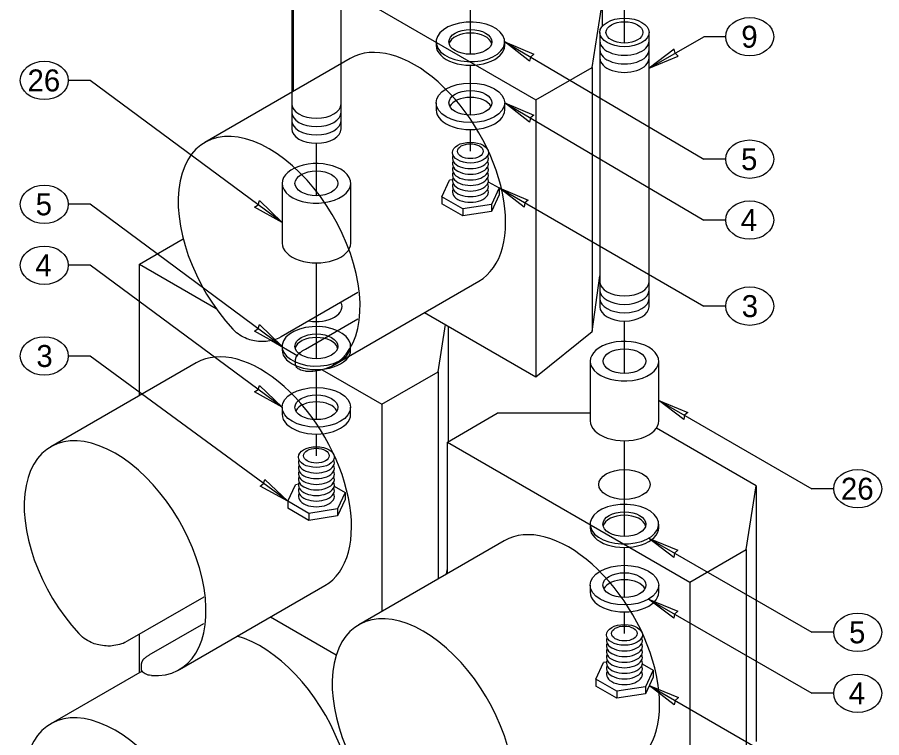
# Model space of a CAD drawing. Extents: x 99862 to 104211, y 98939 to 105076.
# Drawn here: x 100722 to 101352, y 103733 to 104258 of the extents above; entities that cross this region are included whole.
import ezdxf

# ---------------------------------------------------------------- set-up
doc = ezdxf.new("R2010")
doc.units = 0
for name, color, linetype in [('Level 11', 7, 'Continuous'), ('Level 15', 7, 'Continuous'), ('Level 19', 7, 'Continuous'), ('Level 2', 7, 'Continuous'), ('Level 20', 7, 'Continuous'), ('Level 26', 7, 'Continuous'), ('Level 3', 7, 'Continuous'), ('Level 4', 7, 'Continuous'), ('Level 5', 7, 'Continuous'), ('Level 7', 7, 'Continuous'), ('Level 9', 7, 'Continuous')]:
    doc.layers.add(name, color=color, linetype=linetype)

msp = doc.modelspace()

# ---------------------------------------------------------------- linework, layer by layer
at = {"layer": 'Level 11'}
for p, q in [((101027.62, 104240.09), (101027.62, 104237.54)), ((101077.62, 104237.54), (101077.62, 104240.09)), ((101027.62, 104195.66), (101027.62, 104190.56)), ((101077.62, 104190.56), (101077.62, 104195.66)), ((100915.33, 104018.13), (100915.33, 104015.58)), ((100965.33, 104015.58), (100965.33, 104018.13)), ((100915.33, 103973.7), (100915.33, 103968.6)), ((100965.33, 103968.6), (100965.33, 103973.7)), ((101139.89, 103888.48), (101139.89, 103885.93)), ((101189.89, 103885.93), (101189.89, 103888.48)), ((101139.89, 103844.06), (101139.89, 103838.95)), ((101189.89, 103838.95), (101189.89, 103844.06))]:
    msp.add_line(p, q, dxfattribs=at)
for centre in [(101052.62, 104240.09), (101052.62, 104195.66), (100940.33, 104018.13), (100940.33, 103973.7), (101164.89, 103888.48), (101164.89, 103844.06)]:
    msp.add_ellipse(centre, major_axis=(15.62, 0), ratio=0.57735, dxfattribs=at)
for centre, major_axis, start_param, end_param in [((101052.62, 104237.54), (-15.62, 0), 3.28349, 6.141288), ((101052.62, 104237.54), (-25, 0), 0, 3.141593), ((101052.62, 104190.56), (-15.62, 0), 3.428349, 5.996429), ((101052.62, 104190.56), (-25, 0), 6.283185, 9.424778), ((100940.33, 104015.58), (-15.62, 0), 3.28349, 6.141288), ((100940.33, 104015.58), (-25, 0), 0, 3.141593), ((100940.33, 103968.6), (-15.62, 0), 3.428349, 5.996429), ((100940.33, 103968.6), (-25, 0), 6.283185, 9.424778), ((101164.89, 103885.93), (-15.62, 0), 3.28349, 6.141288), ((101164.89, 103885.93), (-25, 0), 0, 3.141593), ((101164.89, 103838.95), (-15.62, 0), 3.428349, 5.996429), ((101164.89, 103838.95), (-25, 0), 6.283185, 9.424778)]:
    msp.add_ellipse(centre, major_axis=major_axis, ratio=0.57735, start_param=start_param, end_param=end_param, dxfattribs=at)
at = {"layer": 'Level 15'}
for p, q in [((101052.62, 104231.07), (101052.62, 104353.08)), ((101164.89, 104239.21), (101164.89, 104281.96)), ((101077.62, 104240.09), (101222.73, 104154.6)), ((101182.95, 104220.9), (101222.73, 104243.87)), ((101238.73, 104243.87), (101222.73, 104243.87)), ((101052.62, 104186.64), (101052.62, 104223.11)), ((100775.49, 104212), (100759.49, 104212)), ((100915.38, 104108.43), (100775.49, 104212)), ((101077.62, 104195.66), (101222.73, 104110.18)), ((101052.62, 104160.39), (101052.62, 104176.13)), ((100940.33, 104127.95), (100940.33, 104166.23)), ((101238.73, 104154.6), (101222.73, 104154.6)), ((101073.53, 104133.61), (101222.73, 104047.44)), ((100775.49, 104121.67), (100759.49, 104121.67)), ((100915.33, 104018.13), (100775.49, 104121.67)), ((101238.73, 104110.18), (101222.73, 104110.18)), ((100775.49, 104077.25), (100759.49, 104077.25)), ((100915.33, 103973.7), (100775.49, 104077.25)), ((100940.33, 104009.11), (100940.33, 104078.97)), ((101238.73, 104047.44), (101222.73, 104047.44)), ((101164.89, 103998.3), (101164.89, 104036.59)), ((100775.49, 104011.08), (100759.49, 104011.08)), ((100919.42, 103905.18), (100775.49, 104011.08)), ((100940.33, 103964.68), (100940.33, 104001.14)), ((101189.95, 103978.73), (101301.48, 103914.33)), ((100940.33, 103938.42), (100940.33, 103954.17)), ((101164.89, 103879.46), (101164.89, 103949.33)), ((101317.48, 103914.33), (101301.48, 103914.33)), ((101182.57, 103878.28), (101301.48, 103809.63)), ((101164.89, 103835.04), (101164.89, 103871.5)), ((101182.57, 103833.85), (101301.48, 103765.2)), ((101164.89, 103808.78), (101164.89, 103824.52)), ((101317.48, 103809.63), (101301.48, 103809.63)), ((101183.01, 103770.87), (101301.48, 103702.47)), ((101317.48, 103765.2), (101301.48, 103765.2))]:
    msp.add_line(p, q, dxfattribs=at)
for points in [[(101077.62, 104240.09), (101098.8, 104231.08), (101096.38, 104229.04), (101095.77, 104225.93)], [(101182.95, 104220.9), (101204.21, 104229.73), (101201.81, 104231.79), (101201.23, 104234.9)], [(101077.62, 104195.66), (101098.8, 104186.65), (101096.38, 104184.61), (101095.77, 104181.5)], [(101073.53, 104133.61), (101094.79, 104124.78), (101092.38, 104122.73), (101091.81, 104119.61)], [(100915.38, 104108.43), (100895.26, 104119.61), (100897.88, 104121.39), (100898.81, 104124.41)], [(100915.33, 104018.13), (100895.21, 104029.31), (100897.83, 104031.09), (100898.76, 104034.11)], [(100915.33, 103973.7), (100895.21, 103984.89), (100897.83, 103986.66), (100898.76, 103989.69)], [(101189.95, 103978.73), (101211.21, 103969.9), (101208.8, 103967.84), (101208.22, 103964.73)], [(100919.42, 103905.18), (100899.26, 103916.31), (100901.88, 103918.09), (100902.8, 103921.12)], [(101182.57, 103878.28), (101203.84, 103869.45), (101201.43, 103867.39), (101200.85, 103864.28)], [(101182.57, 103833.85), (101203.84, 103825.02), (101201.43, 103822.96), (101200.85, 103819.85)], [(101183.01, 103770.87), (101204.27, 103762.04), (101201.86, 103759.98), (101201.28, 103756.87)]]:
    msp.add_lwpolyline(points, close=True, dxfattribs=at)
at = {"layer": 'Level 19'}
for p, q in [((101141.29, 104029.03), (101146.95, 104069.49)), ((101100.34, 103995.93), (101141.29, 104029.03)), ((101035.32, 103852.16), (101035.84, 103855.87))]:
    msp.add_line(p, q, dxfattribs=at)
at = {"layer": 'Level 2'}
for p, q in [((101073.53, 104133.61), (101067.93, 104121.54)), ((101047.01, 104118.31), (101031.7, 104127.14)), ((101067.93, 104121.54), (101047.01, 104118.31)), ((101067.93, 104121.54), (101067.93, 104116.44)), ((101047.01, 104118.31), (101047.01, 104113.2)), ((100961.24, 103911.65), (100955.64, 103899.58)), ((100934.73, 103896.34), (100919.42, 103905.18)), ((100955.64, 103899.58), (100934.73, 103896.34)), ((100955.64, 103899.58), (100955.64, 103894.48)), ((100934.73, 103896.34), (100934.73, 103891.24)), ((101185.81, 103782.01), (101180.2, 103769.93)), ((101159.29, 103766.7), (101143.98, 103775.54)), ((101180.2, 103769.93), (101159.29, 103766.7)), ((101159.29, 103766.7), (101159.29, 103761.6)), ((101180.2, 103769.93), (101180.2, 103764.83))]:
    msp.add_line(p, q, dxfattribs=at)
for centre in [(101052.62, 104160.39), (100940.33, 103938.42), (101164.89, 103808.78)]:
    msp.add_ellipse(centre, major_axis=(-9.38, 0), ratio=0.57735, dxfattribs=at)
for centre, start_param, end_param in [((101052.62, 104155.28), 2.86885, 6.555928), ((101052.62, 104151.2), 2.86885, 6.555928), ((101052.62, 104147.04), 2.86338, 6.561398), ((101052.62, 104143.04), 2.874311, 6.550467), ((101052.62, 104138.95), 2.86885, 6.555928), ((101052.62, 104134.87), 2.86885, 6.555928), ((100940.33, 103933.32), 2.86885, 6.555928), ((100940.33, 103929.24), 2.86885, 6.555928), ((100940.33, 103925.08), 2.86338, 6.561398), ((100940.33, 103916.99), 2.86885, 6.555928), ((100940.33, 103921.07), 2.874311, 6.550467), ((100940.33, 103912.91), 2.86885, 6.555928), ((101164.89, 103803.68), 2.86885, 6.555928), ((101164.89, 103799.59), 2.86885, 6.555928), ((101164.89, 103795.43), 2.86338, 6.561398), ((101164.89, 103791.43), 2.874311, 6.550467), ((101164.89, 103787.35), 2.86885, 6.555928), ((101164.89, 103783.26), 2.86885, 6.555928)]:
    msp.add_ellipse(centre, major_axis=(13.12, 0), ratio=0.57735, start_param=start_param, end_param=end_param, dxfattribs=at)
at = {"layer": 'Level 20'}
for centre in [(101256.23, 104243.87), (100741.99, 104212), (101256.23, 104154.6), (100741.99, 104121.67), (101256.23, 104110.18), (100741.99, 104077.25), (101256.23, 104047.44), (100741.99, 104011.08), (101334.98, 103914.33), (101334.98, 103809.63), (101334.98, 103765.2)]:
    msp.add_ellipse(centre, major_axis=(-17.5, 0), ratio=0.8, dxfattribs=at)
at = {"layer": 'Level 26'}
for p, q in [((100923.56, 104204.06), (100923.56, 104299.94)), ((100923.56, 104299.94), (101100.34, 104197.87)), ((101141.29, 104221.52), (101148.63, 104268.14)), ((101148.63, 104268.14), (101148.63, 104251.39)), ((100965.07, 104228.03), (100859.01, 104166.79)), ((101100.34, 104197.87), (101141.29, 104221.52)), ((101141.29, 104221.52), (101141.29, 104029.03)), ((101100.34, 104197.87), (101100.34, 103995.93)), ((100811.28, 104077.98), (100843.31, 104096.47)), ((100811.28, 103982.11), (100811.28, 104077.98)), ((100811.28, 104077.98), (100867.3, 104045.63)), ((100952.76, 104004.42), (101058.82, 104065.65)), ((100970.59, 104057.31), (100914.72, 104025.05)), ((100932.4, 104016.13), (100970.47, 104038.11)), ((101019.2, 104042.77), (101100.34, 103995.93)), ((101029.02, 103999.56), (101034.43, 104033.97)), ((101036.36, 104032.87), (101036.36, 103948.63)), ((100907.62, 104022.35), (100926.74, 104011.32)), ((100852.79, 104006.07), (100746.73, 103944.84)), ((100925.08, 104005.69), (100925.08, 104007)), ((100944.46, 104001.08), (100988.06, 103975.91)), ((100988.06, 103975.91), (101029.02, 103999.56)), ((101029.02, 103999.56), (101029.02, 103848.52)), ((100988.06, 103975.91), (100988.06, 103824.87)), ((101035.84, 103948.33), (101072.16, 103969.3)), ((101139.95, 103969.3), (101072.16, 103969.3)), ((101260.91, 103916.53), (101188.22, 103958.5)), ((101035.84, 103852.46), (101035.84, 103948.33)), ((101035.84, 103948.33), (101212.62, 103846.27)), ((101253.57, 103869.91), (101260.91, 103916.53)), ((101260.91, 103916.53), (101260.91, 103729.92)), ((101077.35, 103876.42), (100971.29, 103815.19)), ((101212.62, 103846.27), (101253.57, 103869.91)), ((101253.57, 103869.91), (101253.57, 103677.43)), ((100840.48, 103782.46), (100946.54, 103843.69)), ((101212.62, 103846.27), (101212.62, 103644.32)), ((100858.31, 103835.35), (100802.44, 103803.09)), ((100906.92, 103820.81), (100954.82, 103793.16)), ((100906.92, 103820.81), (100954.82, 103793.16)), ((100820.12, 103794.17), (100858.19, 103816.15)), ((100811.28, 103780.16), (100811.28, 103808.2)), ((100813.42, 103781.39), (100746.73, 103742.89)), ((100812.8, 103783.73), (100812.8, 103785.04))]:
    msp.add_line(p, q, dxfattribs=at)
for centre, major_axis, start_param, end_param in [((101011.95, 104146.84), (46.88, -81.19), 0, 3.141593), ((100905.88, 104085.6), (46.88, -81.19), 5.909304, 11.369456), ((100940.34, 104047.05), (18.75, 0), 4.417653, 6.577921), ((100899.67, 103924.88), (46.88, -81.19), 0, 3.141593), ((100793.6, 103863.65), (46.88, -81.19), 5.909304, 11.369456), ((101124.23, 103795.23), (46.88, -81.19), 0, 3.141593), ((101018.16, 103734), (46.88, -81.19), 5.909304, 11.369456), ((100899.67, 103722.94), (46.88, -81.19), 0, 2.616954), ((100793.6, 103661.7), (46.88, -81.19), 5.909304, 11.369456)]:
    msp.add_ellipse(centre, major_axis=major_axis, ratio=0.57735, start_param=start_param, end_param=end_param, dxfattribs=at)
msp.add_ellipse((101164.89, 103917.41), major_axis=(18.75, 0), ratio=0.57735, dxfattribs=at)
msp.add_ellipse((101164.89, 103917.41), major_axis=(18.75, 0), ratio=0.57735, dxfattribs=at)
for points, degree in [([(100914.72, 104025.05), (100912.33, 104023.67), (100909.5, 104022.66), (100903.3, 104021.55), (100899.94, 104021.47), (100893.36, 104022.38), (100890.08, 104023.38), (100884.2, 104026.39), (100881.55, 104028.39), (100879.37, 104030.76)], 3), ([(100925.08, 104006.98), (100925.08, 104009.89), (100927.71, 104013.43), (100932.4, 104016.13)], 2), ([(100932.4, 104000.14), (100930.21, 104000.3), (100928.41, 104000.86), (100925.85, 104002.73), (100925.13, 104004.02), (100925.08, 104005.54), (100925.08, 104005.59), (100925.08, 104005.64)], 3), ([(100802.44, 103803.09), (100800.05, 103801.71), (100797.22, 103800.71), (100791.02, 103799.59), (100787.66, 103799.51), (100781.08, 103800.42), (100777.8, 103801.43), (100771.92, 103804.43), (100769.28, 103806.43), (100767.09, 103808.8)], 3), ([(100812.8, 103785.02), (100812.8, 103787.93), (100815.43, 103791.47), (100820.12, 103794.17)], 2), ([(100820.12, 103778.18), (100817.93, 103778.34), (100816.13, 103778.9), (100813.57, 103780.77), (100812.86, 103782.06), (100812.8, 103783.59), (100812.8, 103783.63), (100812.8, 103783.68)], 3)]:
    msp.add_open_spline(points, degree=degree, dxfattribs=at)
at = {"layer": 'Level 3'}
for p, q in [((101031.7, 104127.14), (101037.31, 104139.22)), ((101039.53, 104139.56), (101037.31, 104139.22)), ((101065.67, 104138.15), (101073.53, 104133.61)), ((101073.53, 104133.61), (101073.53, 104128.51)), ((101031.7, 104127.14), (101031.7, 104122.04)), ((101073.53, 104128.51), (101067.93, 104116.44)), ((101047.01, 104113.2), (101031.7, 104122.04)), ((101067.93, 104116.44), (101047.01, 104113.2)), ((100927.25, 103917.6), (100925.02, 103917.26)), ((100919.42, 103905.18), (100925.02, 103917.26)), ((100953.38, 103916.19), (100961.24, 103911.65)), ((100961.24, 103911.65), (100961.24, 103906.55)), ((100919.42, 103905.18), (100919.42, 103900.08)), ((100961.24, 103906.55), (100955.64, 103894.48)), ((100934.73, 103891.24), (100919.42, 103900.08)), ((100955.64, 103894.48), (100934.73, 103891.24)), ((101143.98, 103775.54), (101149.59, 103787.61)), ((101151.81, 103787.96), (101149.59, 103787.61)), ((101177.95, 103786.55), (101185.81, 103782.01)), ((101185.81, 103782.01), (101185.81, 103776.9)), ((101143.98, 103775.54), (101143.98, 103770.43)), ((101185.81, 103776.9), (101180.2, 103764.83)), ((101159.29, 103761.6), (101143.98, 103770.43)), ((101180.2, 103764.83), (101159.29, 103761.6))]:
    msp.add_line(p, q, dxfattribs=at)
for centre in [(101052.62, 104159.37), (100940.33, 103937.4), (101164.89, 103807.76)]:
    msp.add_ellipse(centre, major_axis=(13.12, 0), ratio=0.57735, dxfattribs=at)
for centre in [(101052.62, 104130.7), (100940.33, 103908.74), (101164.89, 103779.09)]:
    msp.add_ellipse(centre, major_axis=(13.12, 0), ratio=0.57735, start_param=2.862617, end_param=6.56216, dxfattribs=at)
at = {"layer": 'Level 4'}
for centre in [(101052.62, 104195.66), (100940.33, 103973.7), (101164.89, 103844.06)]:
    msp.add_ellipse(centre, major_axis=(25, 0), ratio=0.57735, dxfattribs=at)
at = {"layer": 'Level 5'}
for centre in [(101052.62, 104240.09), (100940.33, 104018.13), (101164.89, 103888.48)]:
    msp.add_ellipse(centre, major_axis=(25, 0), ratio=0.57735, start_param=1.690716, end_param=7.973165, dxfattribs=at)
at = {"layer": 'Level 7'}
for p, q in [((100915.38, 104136.97), (100915.38, 104093.41)), ((100965.38, 104093.41), (100965.38, 104136.97)), ((101139.95, 104007.32), (101139.95, 103963.76)), ((101189.95, 103963.76), (101189.95, 104007.32))]:
    msp.add_line(p, q, dxfattribs=at)
for centre, start_param, end_param in [((100940.38, 104136.97), 3.927598, 6.283185), ((100940.38, 104136.97), 0, 3.927598), ((100940.38, 104093.41), 0, 3.141593), ((101164.95, 104007.32), 3.927598, 6.283185), ((101164.95, 104007.32), 0, 3.927598), ((101164.95, 103963.76), 0, 3.141593)]:
    msp.add_ellipse(centre, major_axis=(-25, 0), ratio=0.57735, start_param=start_param, end_param=end_param, dxfattribs=at)
for centre in [(100940.38, 104136.97), (101164.95, 104007.32)]:
    msp.add_ellipse(centre, major_axis=(-15.63, 0), ratio=0.57735, dxfattribs=at)
at = {"layer": 'Level 9'}
for p, q in [((100922.39, 104376.65), (100922.39, 104176.62)), ((100958.39, 104176.62), (100958.39, 104376.65)), ((101146.95, 104247), (101146.95, 104046.98)), ((101182.95, 104046.98), (101182.95, 104247))]:
    msp.add_line(p, q, dxfattribs=at)
for major_axis in [(18, 0), (13.5, 0)]:
    msp.add_ellipse((101164.95, 104247), major_axis=major_axis, ratio=0.57735, dxfattribs=at)
for centre, start_param in [((101164.95, 104240.72), 3.141588), ((101164.95, 104234.4), 3.141587), ((101164.95, 104228.27), 3.141585), ((100940.39, 104194.9), 3.141593), ((100940.39, 104188.77), 3.141593), ((100940.39, 104182.64), 3.141593), ((100940.39, 104176.62), 3.141593), ((101164.95, 104065.26), 3.141593), ((101164.95, 104059.12), 3.141593), ((101164.95, 104052.99), 3.141593), ((101164.95, 104046.98), 3.141593)]:
    msp.add_ellipse(centre, major_axis=(18, 0), ratio=0.57735, start_param=start_param, end_param=6.283185, dxfattribs=at)

# ---------------------------------------------------------------- texts
at = {"layer": 'Level 20'}
for s, p in [('9', (101250.14, 104235.87)), ('26', (100729.78, 104204)), ('5', (101249.92, 104146.61)), ('5', (100735.67, 104113.67)), ('4', (101249.72, 104102.18)), ('4', (100735.47, 104069.25)), ('3', (101250.45, 104039.45)), ('3', (100736.2, 104003.09)), ('26', (101322.78, 103906.33)), ('5', (101328.67, 103801.63)), ('4', (101328.47, 103757.2))]:
    msp.add_text(s, height=16, dxfattribs=at).set_placement(p)

doc.saveas('drawing.dxf')
